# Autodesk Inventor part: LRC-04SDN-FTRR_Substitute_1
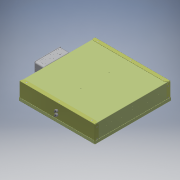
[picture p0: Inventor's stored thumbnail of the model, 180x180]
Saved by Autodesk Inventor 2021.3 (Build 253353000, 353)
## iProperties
Part Number: LRC-04SDN-FTRR_Substitute_1
Material: Generic
Document SubType Name: Modeling
Designer: JChurch
Manufacturer: Standard
Standards Organization: Custom
Density: 1 g/cm^3
Appearance: Smooth - Black
Author: JChurch
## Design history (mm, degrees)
derived "LRC-04SDN-FTRR.iam"
body "Solid9"
node "885000-00-00.iam:1::830000-00-00.ipt:1"
node "885000-00-00.iam:1::509424-00-00.ipt:1"
body "Solid10"
node "885000-00-00.iam:1::830593-00-00.ipt:1"
body "Solid11"
node "885000-00-00.iam:1::506002-00-00.ipt:1"
body "Solid12"
node "885000-00-00.iam:1::506002-00-00.ipt:2"
body "Solid13"
node "885000-00-00.iam:1::506002-00-00.ipt:3"
body "Solid14"
node "885000-00-00.iam:1::506002-00-00.ipt:4"
body "Solid15"
node "885000-00-00.iam:1::506002-00-00.ipt:5"
body "Solid16"
node "885000-00-00.iam:1::506002-00-00.ipt:6"
body "Solid17"
node "885000-00-00.iam:1::506002-00-00.ipt:7"
body "Solid18"
node "885000-00-00.iam:1::506002-00-00.ipt:8"
body "Solid19"
node "885000-00-00.iam:1::506002-00-00.ipt:9"
body "Solid20"
node "885000-00-00.iam:1::506002-00-00.ipt:10"
body "Solid21"
node "885000-00-00.iam:1::506002-00-00.ipt:11"
body "Solid22"
node "885000-00-00.iam:1::506002-00-00.ipt:12"
body "Solid23"
node "885000-00-00.iam:1::506002-00-00.ipt:13"
body "Solid24"
node "885000-00-00.iam:1::506002-00-00.ipt:14"
body "Solid25"
node "885000-00-00.iam:1::500027-00-00.ipt:1"
body "Solid26"
node "885000-00-00.iam:1::500027-00-00.ipt:2"
body "Solid27"
node "885000-00-00.iam:1::502116-00-00.ipt:1"
body "Solid28"
node "885000-00-00.iam:1::502116-00-00.ipt:2"
body "Solid29"
node "885000-00-00.iam:1::501030-00-00.ipt:1"
body "Solid30"
node "885000-00-00.iam:1::501030-00-00.ipt:2"
body "Solid31"
node "885000-00-00.iam:1::501030-00-00.ipt:3"
body "Solid32"
node "885000-00-00.iam:1::501030-00-00.ipt:4"
body "Solid33"
node "885000-00-00.iam:1::500027-00-00.ipt:3"
body "Solid34"
node "885000-00-00.iam:1::500027-00-00.ipt:4"
body "Solid35"
node "885000-00-00.iam:1::501030-00-00.ipt:5"
body "Solid36"
node "885000-00-00.iam:1::500027-00-00.ipt:5"
body "Solid37"
node "885000-00-00.iam:1::501030-00-00.ipt:6"
body "Solid38"
node "885000-00-00.iam:1::500027-00-00.ipt:6"
body "Solid39"
node "885000-00-00.iam:1::830593-00-00.ipt:2"
body "Solid40"
node "885000-00-00.iam:1::507032-00-00.ipt:1"
body "Solid41"
node "885000-00-00.iam:1::640042-00-03.ipt:1"
body "Solid42"
node "885000-00-00.iam:1::501030-00-00.ipt:9"
body "Solid43"
node "885000-00-00.iam:1::501030-00-00.ipt:10"
body "Solid44"
node "885000-00-00.iam:1::501030-00-00.ipt:11"
body "Solid45"
node "885000-00-00.iam:1::501030-00-00.ipt:12"
body "Solid46"
node "885000-00-00.iam:1::503031-00-00.ipt:1"
body "Solid47"
node "885000-00-00.iam:1::503031-00-00.ipt:2"
body "Solid48"
node "885000-00-00.iam:1::509425-00-00.ipt:1"
body "Solid49"
node "830520-00-00.ipt:1"
body "Solid50"
node "750480-FT-XX.iam:1::740103-50-00.ipt:1"
body "Solid51"
node "750480-FT-XX.iam:1::507035-01-38.ipt:1"
body "Solid52"
node "750480-FT-XX.iam:1::510051-00-00.ipt:1"
body "Solid53"
node "750480-FT-XX.iam:1::700483-01-20.ipt:1"
body "Solid54"
node "750480-FT-XX.iam:1::502040-00-00.ipt:1"
body "Solid55"
node "750480-FT-XX.iam:1::725379-00-00.ipt:1"
body "Solid56"
node "750480-FT-XX.iam:1::507035-01-38.ipt:2"
body "Solid57"
node "750480-FT-XX.iam:1::502040-00-00.ipt:2"
body "Solid58"
node "750480-FT-XX.iam:1::510052-00-00_65.ipt:1"
body "Solid59"
other parameters: "d15" = 61.595, "d16" = 9.525, "d17" = 9.525, "d35" = 5.08
